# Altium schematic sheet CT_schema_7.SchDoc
size 300 x 247 mm
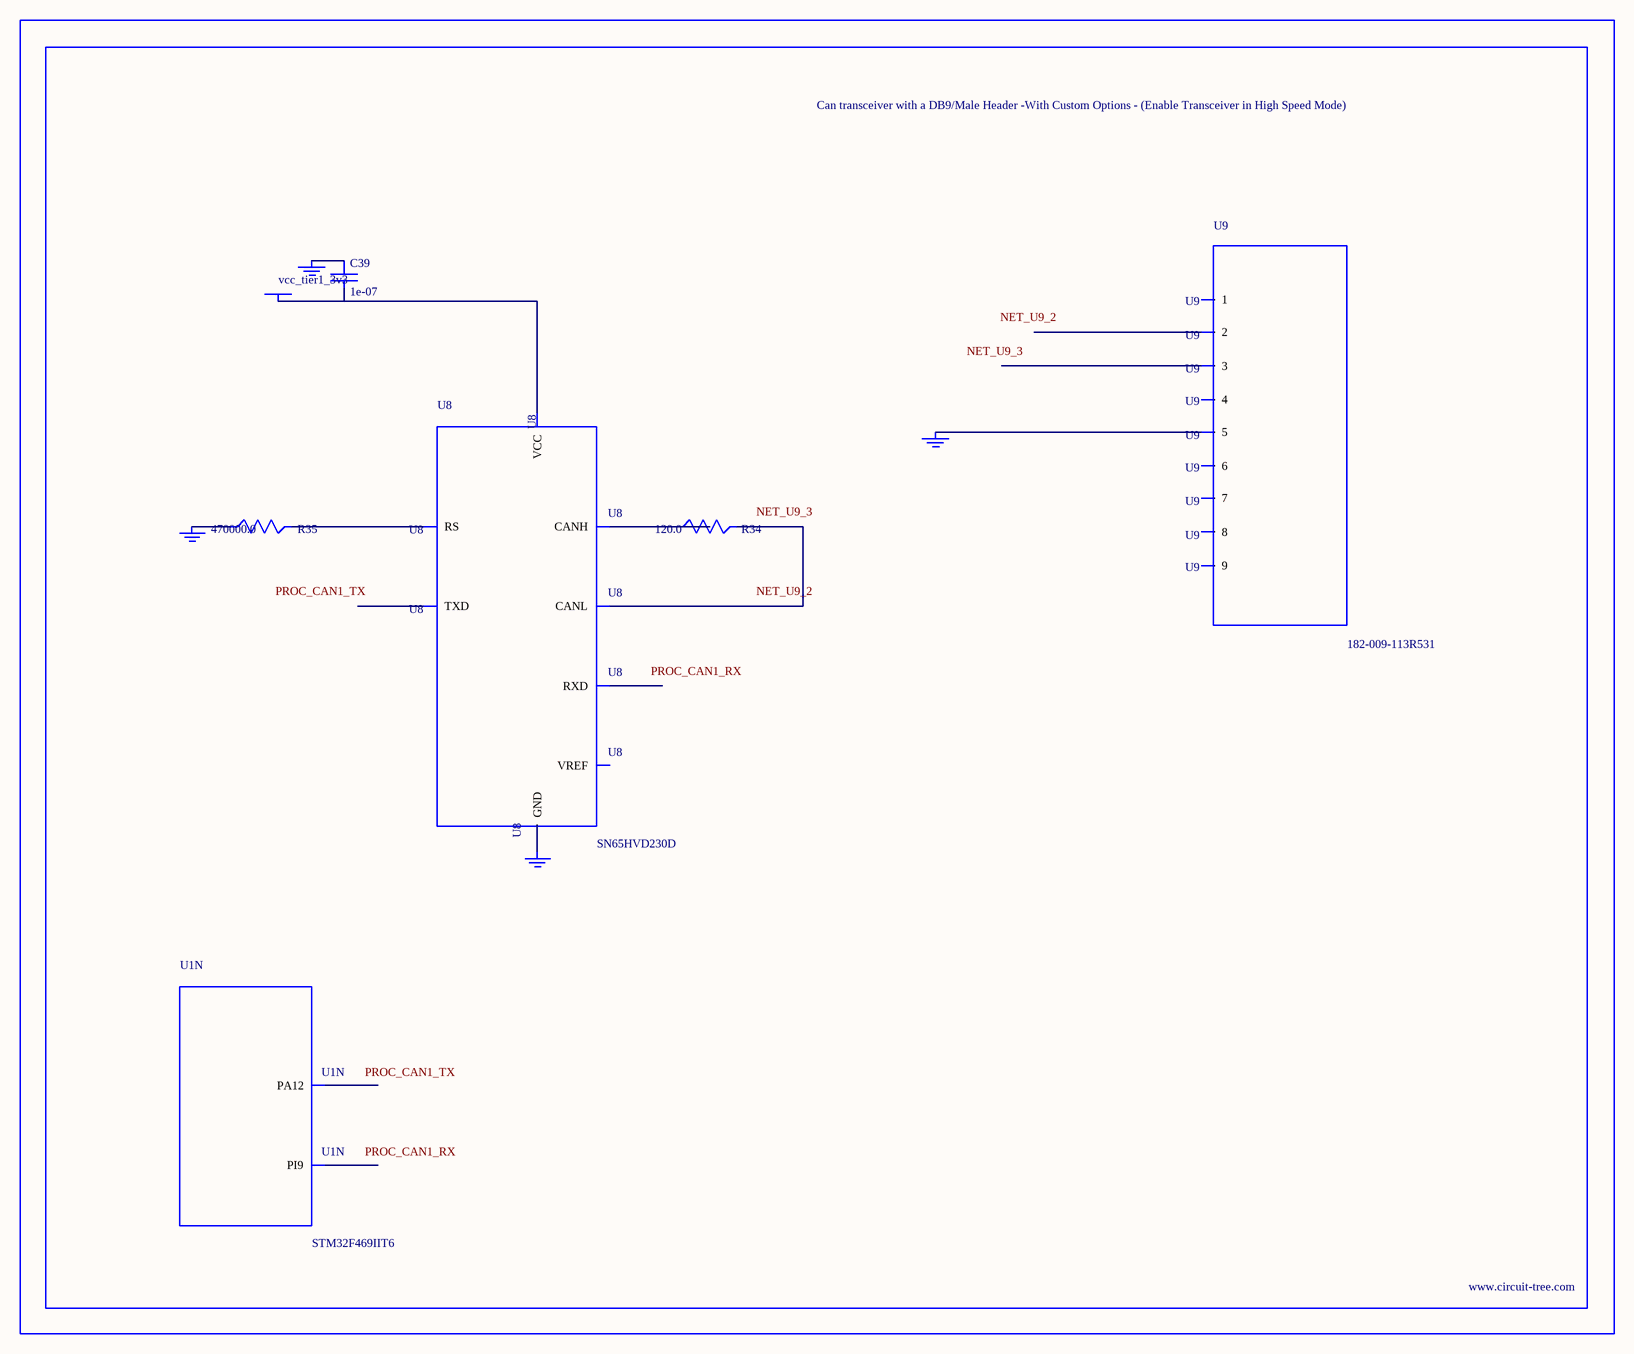
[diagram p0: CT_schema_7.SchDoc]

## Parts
BORDER6  (no value)
C39  1e-07  [C0402]
GND_INSTANCE_6_0  (no value)
GND_INSTANCE_6_1  (no value)
GND_INSTANCE_6_2  (no value)
GND_INSTANCE_6_3  (no value)
POWER_INSTANCE_6_0  vcc_tier1_3v3
R34  120.0  [R0603]
R35  470000.0  [R0603]
U1  STM32F469IIT6  [LQFP176]  (part N of 14)
U8  SN65HVD230D  [SOIC-8]
U9  182-009-113R531  [182-009-MALE]

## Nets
NetC39_1: C39.1 GND_INSTANCE_6_0.0(GND)
NetC39_2: C39.2 POWER_INSTANCE_6_0.0(PWR) U8.3(VCC)
NetGND_INSTANCE_6_1_0: GND_INSTANCE_6_1.0(GND) R35.1
NetGND_INSTANCE_6_2_0: GND_INSTANCE_6_2.0(GND) U8.2(GND)
NetGND_INSTANCE_6_3_0: GND_INSTANCE_6_3.0(GND) U9.5
NetR34_1: R34.1 U8.7(CANH)
NetR34_2: R34.2 U8.6(CANL)
NetR35_2: R35.2 U8.8(RS)

Not connected (* = marked no-connect by the designer): U1 11(PI9) 127(PA12); U8 1(TXD) 4(RXD) 5(VREF); U9 1 2 3 4 6 7 8 9

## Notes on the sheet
- Labels drawn without touching a wire or pin: NET_U9_2, NET_U9_3, PROC_CAN1_RX, PROC_CAN1_TX

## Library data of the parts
BORDER6 = BORDER_PAGE6
C39 = C0402C104K3RACTU
GND_INSTANCE_6_0-GND_INSTANCE_6_3 = GND
POWER_INSTANCE_6_0 = PWR
R34 = RC0603JR-07120RL
R35 = RC0603JR-07470KL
